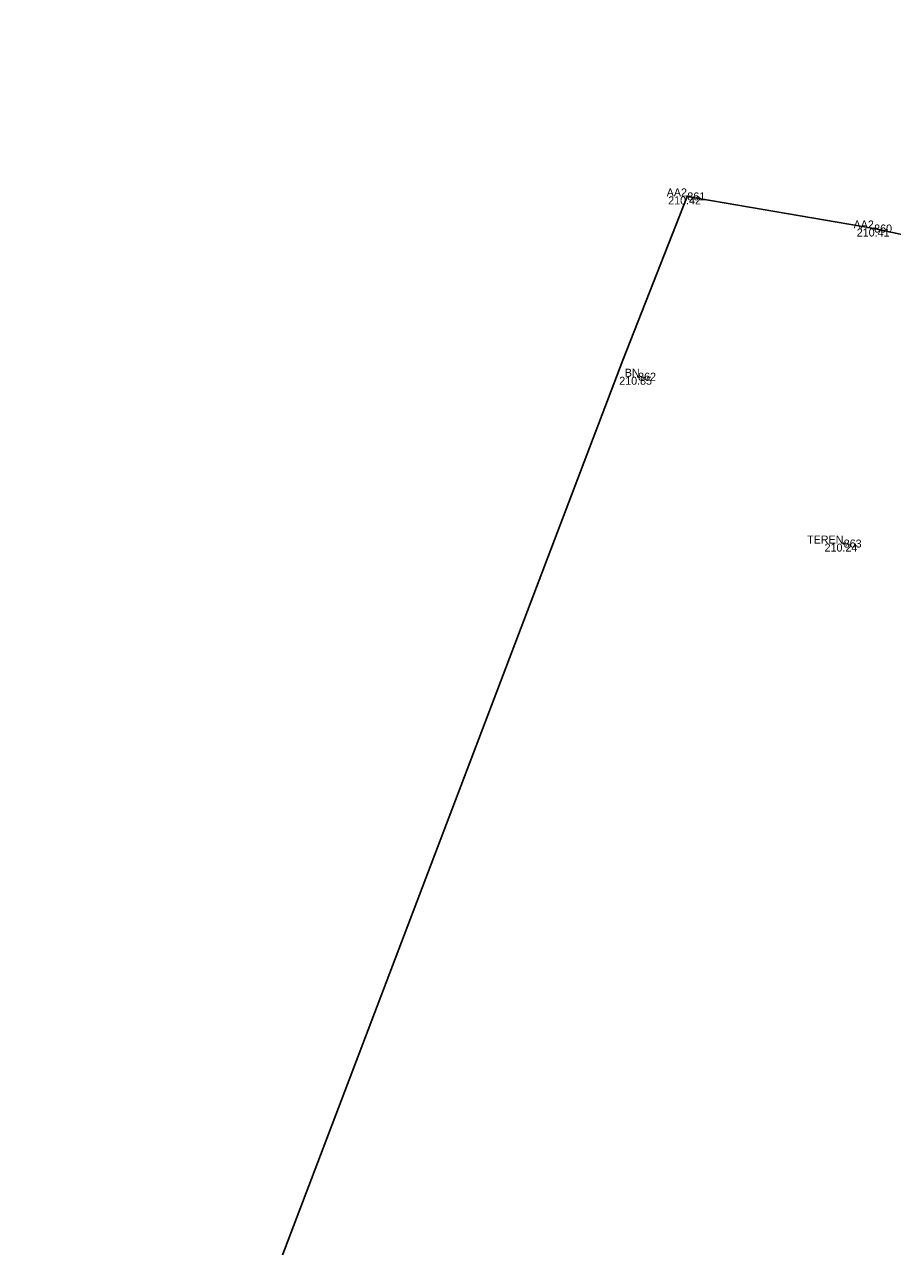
# Model space of a CAD drawing. Extents: x -263091 to -262565, y -1238731 to -1237092.
# Drawn here: x -262808.34 to -262786.65, y -1237649.19 to -1237618.65 of the extents above; entities that cross this region are included whole.
import ezdxf

# ---------------------------------------------------------------- set-up
doc = ezdxf.new("R2010")
doc.units = 0
for name, color, linetype in [('03_Asfalt', 7, 'Continuous'), ('11_Hranica_KN', 7, 'Continuous'), ('Groma (21)', 7, 'Continuous'), ('Groma (22)', 7, 'Continuous'), ('Groma (23)', 7, 'Continuous'), ('Groma (24)', 7, 'Continuous'), ('U005_Zeleň_mimo', 7, 'Continuous')]:
    doc.layers.add(name, color=color, linetype=linetype)

msp = doc.modelspace()

# ---------------------------------------------------------------- linework, layer by layer
at = {"layer": '03_Asfalt'}
msp.add_lwpolyline([(-262768.342, -1237527.637), (-262773.935, -1237562.141), (-262778.136, -1237587.835), (-262781.33, -1237608.146), (-262784.132, -1237624.399), (-262787.108, -1237623.753), (-262791.777, -1237622.951)], dxfattribs=at)
at = {"layer": '11_Hranica_KN'}
msp.add_lwpolyline([(-262808.336, -1237666.357), (-262793.39, -1237627.04), (-262791.777, -1237622.951)], dxfattribs=at)
at = {"layer": 'Groma (21)'}
for centre in [(-262791.777, -1237622.951), (-262787.108, -1237623.753), (-262793.005, -1237627.457), (-262787.869, -1237631.626)]:
    msp.add_circle(centre, 0.01, dxfattribs=at)
at = {"layer": 'U005_Zeleň_mimo'}
msp.add_lwpolyline([(-262747.68, -1237500.55), (-262747.82, -1237524.57), (-262747.79, -1237545.2), (-262748.22, -1237555.41), (-262749.02, -1237564.32), (-262749.97, -1237571.23), (-262751.77, -1237579.93), (-262754.83, -1237588.44), (-262759.49, -1237598.41), (-262767.84, -1237616), (-262778.34, -1237638.1), (-262786.05, -1237653.78), (-262793.97, -1237669.78), (-262795.54, -1237672.75), (-262808.34, -1237666.36), (-262793.39, -1237627.04), (-262791.78, -1237622.95), (-262787.11, -1237623.75), (-262784.13, -1237624.4), (-262781.33, -1237608.15), (-262778.14, -1237587.84), (-262773.94, -1237562.14), (-262768.34, -1237527.64), (-262757.02, -1237455.96)], dxfattribs=at)

# ---------------------------------------------------------------- texts
at = {"layer": 'Groma (22)'}
for s, p in [('861', (-262791.777, -1237623.051)), ('860', (-262787.108, -1237623.853)), ('862', (-262793.005, -1237627.557)), ('863', (-262787.869, -1237631.726))]:
    msp.add_text(s, height=0.2, dxfattribs=at).set_placement(p)
at = {"layer": 'Groma (23)'}
for s, p in [('210.42', (-262792.255, -1237623.151)), ('210.41', (-262787.543, -1237623.953)), ('210.85', (-262793.478, -1237627.657)), ('210.24', (-262788.347, -1237631.826))]:
    msp.add_text(s, height=0.2, dxfattribs=at).set_placement(p)
at = {"layer": 'Groma (24)'}
for s, p in [('AA2', (-262792.292, -1237622.951)), ('AA2', (-262787.623, -1237623.753)), ('BN', (-262793.339, -1237627.457)), ('TEREN', (-262788.784, -1237631.626))]:
    msp.add_text(s, height=0.2, dxfattribs=at).set_placement(p)

doc.saveas('drawing.dxf')
